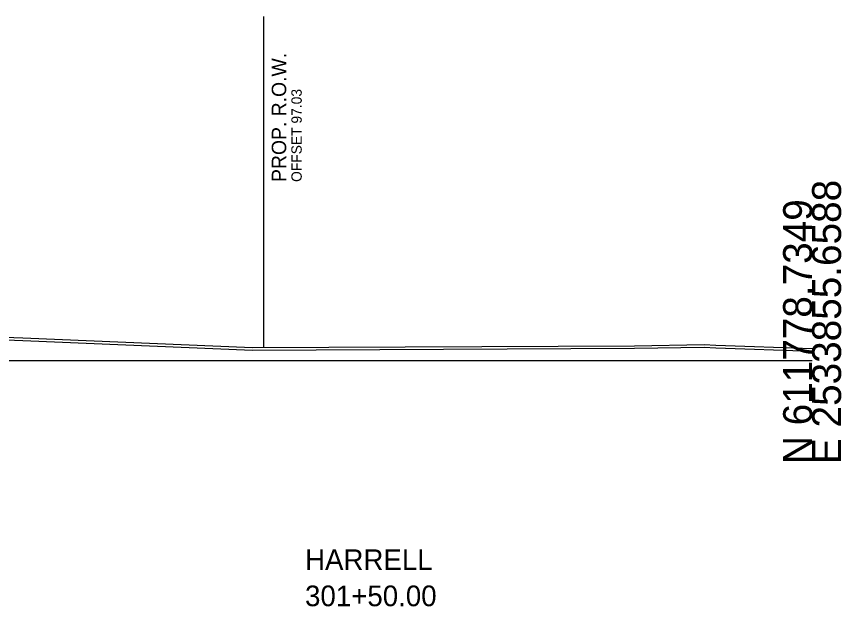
# Model space of a CAD drawing. Extents: x -192 to 2669, y -25 to 8040.
# Drawn here: x 223.1 to 302.8, y 976.2 to 1033.3 of the extents above; entities that cross this region are included whole.
import ezdxf

# ---------------------------------------------------------------- set-up
doc = ezdxf.new("R2010")
doc.units = 0
for name, color, linetype in [('DESIGN - ROW - Right-of-Way and Easement Labels', 7, 'Continuous'), ('DESIGN - ROW - Right-of-Way Linework', 7, 'Continuous'), ('DESIGN - SHEET - Light Grid', 7, 'Continuous'), ('DESIGN - TYPICAL - Warning Text', 7, 'Continuous'), ('SURVEY - GROUND - Bottom of Topsoil Layer', 7, 'Continuous'), ('SURVEY - GROUND - Top of Ground', 7, 'Continuous')]:
    doc.layers.add(name, color=color, linetype=linetype)

msp = doc.modelspace()

# ---------------------------------------------------------------- linework, layer by layer
at = {"layer": 'DESIGN - ROW - Right-of-Way Linework'}
msp.add_line((247.033, 1001.282), (247.033, 1033.282), dxfattribs=at)
at = {"layer": 'DESIGN - SHEET - Light Grid'}
msp.add_line((150, 1000), (300, 1000), dxfattribs=at)
at = {"layer": 'SURVEY - GROUND - Bottom of Topsoil Layer'}
for p, q in [((198.855, 1002.885), (223.733, 1001.963)), ((223.733, 1001.963), (245.932, 1001.027)), ((282.84, 1001.194), (289.554, 1001.3)), ((289.554, 1001.3), (290.689, 1001.253)), ((245.932, 1001.027), (282.84, 1001.194)), ((290.689, 1001.253), (300, 1000.931))]:
    msp.add_line(p, q, dxfattribs=at)
at = {"layer": 'SURVEY - GROUND - Top of Ground'}
msp.add_lwpolyline([(198.855, 1003.135), (223.733, 1002.213), (245.932, 1001.277), (282.84, 1001.444), (289.554, 1001.55), (290.689, 1001.503), (300, 1001.181)], dxfattribs=at)

# ---------------------------------------------------------------- texts
at = {"layer": 'DESIGN - ROW - Right-of-Way and Easement Labels'}
for s, height, p in [('PROP. R.O.W.', 1.4, (249.183, 1017.282)), ('OFFSET 97.03', 1, (250.683, 1017.282))]:
    msp.add_text(s, height=height, rotation=90, dxfattribs=at).set_placement(p)
at = {"layer": 'DESIGN - SHEET - Light Grid'}
for s, p in [('E 2533855.6588', (302.8, 990)), ('N 611778.7349', (300, 990))]:
    msp.add_text(s, height=2.8, rotation=90, dxfattribs=at).set_placement(p)
at = {"layer": 'DESIGN - TYPICAL - Warning Text'}
for s, p in [('HARRELL', (251, 979.75)), ('301+50.00', (251, 976.25))]:
    msp.add_text(s, height=2, dxfattribs=at).set_placement(p)

doc.saveas('drawing.dxf')
